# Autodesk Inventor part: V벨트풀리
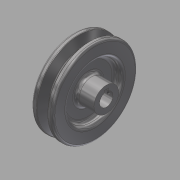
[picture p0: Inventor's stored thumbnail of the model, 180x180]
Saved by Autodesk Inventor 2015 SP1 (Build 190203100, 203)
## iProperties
Created: 2015-11
Part Number: V벨트풀리
Material: 강철, 탄소
Document SubType Name: Modeling
Designer: mduedu
Density: 1 g/cm^3
Appearance: 반광택
Author: mduedu
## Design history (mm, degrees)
sketch "스케치1"
  geometry: L1 (-9.5, 0)-(9.5, 0); L2 (0, 0)-(0, 37.7); L3 (-4.825, 37.7)-(-9.5, 37.7); L4 (-9.5, 37.7)-(-9.5, 0); L5 (0, 28.7)-(-2.074, 28.7); L6 (-2.074, 28.7)-(-4.825, 37.7); L7 (4.825, 37.7)-(9.5, 37.7); L8 (9.5, 37.7)-(9.5, 0); L9 (0, 28.7)-(2.074, 28.7); L10 (2.074, 28.7)-(4.825, 37.7); L11 (-9.5, 35)-(9.5, 35); 3 further points
  constraints: 22 end point, 7 point on line, 4 perpendicular, 3 symmetric about line, 1 coincident, 1 horizontal, 1 horizontal alignment, 1 midpoint, 1 vertical
  dimensions: "d0" = 19 distance of L1.start L1.end; "d2" = 75.4 diameter of L2.end L1 (derived); "d3" = 34 deg angle of L10 L6; "d4" = 6.3 distance between parallel lines of L11 L9; "d5" = 2.7 distance between parallel lines of L7 L11; "d6" = 8 distance of point (4, 35) point (-4, 35); "d7" = 70 diameter of L11 L1
revolve "회전1" sketch "스케치1" stored, may be unused: angle "d8" = 90 deg
sketch "스케치2"
  geometry: C1 r 24 at (0, 0); C2 r 11 at (0, 0); 1 further point
  constraints: 2 centre point, 2 coincident
  dimensions: "d9" = 48 diameter of C1; "d10" = 22 diameter of C2
extrude "돌출1" cut sketch "스케치2" distance "d11" = 6; taper "d12" = 0 deg
extrude "돌출3" join sketch "스케치2" distance "d37" = 10; taper "d38" = 0 deg
fillet "모깎기1" dims "d13" = 3
fillet "모깎기2" dims "d14" = 3
fillet "모깎기3" dims "d15" = 1, "d16" = 0.5, "d17" = 2
hole "구멍1" diameter "d20" = 12; stored, may be unused: countersink angle "d24" = 90 deg, drill point angle "d26" = 118 deg; dims "d21" = 6, "d22" = 4, "d23" = 2, "d25" = 8, "d39" = 10, "d40" = 10
sketch "스케치3"
  geometry: L1 (-2, 0)-(2, 0); L2 (2, 0)-(2, 7.8); L3 (2, 7.8)-(-2, 7.8); L4 (-2, 7.8)-(-2, 0); 2 further points
  constraints: 8 end point, 2 parallel, 1 coincident, 1 horizontal, 1 midpoint, 1 perpendicular
  dimensions: "d27" = 4 distance of L2.end L3.end; "d29" = 7.8 distance of L3.end L1.start
extrude "돌출2" cut sketch "스케치3" stored distance "d30" = 6; taper "d31" = 0 deg
chamfer "모따기1" distance "d32" = 0.5; stored, may be unused: second distance "d33" = 2, angle "d34" = 45 deg
node "작업 평면1"
sketch "스케치4"
  geometry: L1 (-19, 11)-(-19, -11) reference; 2 further points
  constraints: 1 horizontal alignment
  dimensions: "d41" = 25 distance from line of point (6, 0) L1
hole "구멍2" sketch "스케치4" at (6, 0) diameter "d42" = 2.459; stored, may be unused: countersink angle "d46" = 90 deg, drill point angle "d48" = 118 deg; dims "d43" = 6, "d44" = 4, "d45" = 2, "d47" = 8
node "솔리드1"
mirror "대칭1"
